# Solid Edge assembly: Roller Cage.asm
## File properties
Last saved by: Dan
Revision: 48
Project Name: Piston Pump P52
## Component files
Cyl Roller 5-8.par
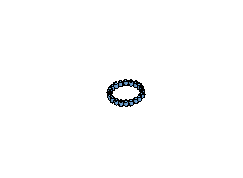
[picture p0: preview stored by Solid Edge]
